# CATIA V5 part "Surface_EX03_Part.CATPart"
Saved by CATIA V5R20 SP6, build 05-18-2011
Part number: Surface_EX03_Part
Bounding box of the stored display mesh (mm): x -17.5 to 17.5, y -55.483 to 14.483, z -21 to 38.531
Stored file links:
  C:\Work\#01 CATIA Lecture Materials\#299 TOYOTA CATIA V5\TOYOTA_CATIA\LCS\Surface\Surface EX03\Surface_EX03_Part.CATPart
  C:\Work\#01 CATIA Lecture Materials\#299 TOYOTA CATIA V5\TOYOTA_CATIA\LCS\Surface\Surface EX03\Surface_EX03.CATProduct
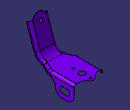
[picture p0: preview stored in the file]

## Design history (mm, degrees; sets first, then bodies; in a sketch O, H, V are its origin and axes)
Set1
  Point1: linked copy from another document
  Line1 to Line3: linked copy from another document
  Point2: linked copy from another document
  Line4 "Line.5": linked copy from another document
  Line5 "Line.6": linked copy from another document
  Line6: linked copy from another document
Set2 "Base"
  Sketch1 on Line3, origin (0, 0, 0), H (0, 1, 0), V (0, 0, 1)
    line L1 (-100, 0) -> (100, 0)
    point P1 (-100, 0)
    point P2 (100, 0)
    distance V P1 = 100
    distance P1 P2 = 200
    coincidence: P1 H
    horizontal: L1 H
  Sketch2 on Line6, origin (0, -50, 30), H (0, 0.9455, 0.3256), V (0, -0.3256, 0.9455)
    line L1 (0, 100) -> (0, -100)
    point P1 (0, 100)
    point P2 (0, -100)
    distance H P1 = 100
    distance P1 P2 = 200
    coincidence: P1 V
    vertical: L1 V
  Extrude1: Lim1 200, Lim2 200, Element1 Sketch2
  Extrude2: Lim1 200, Lim2 200, Element1 Sketch1
Set3 "Base Cut"
  Sketch3 on Line4, origin (0, -50, 30), H (-1, 0, 0), V (0, -0.3256, 0.9455)
    point P1 (-50, 4)
    line L1 (-50, 4) -> (-9.7273, 4)
    arc A1 centre (-0.2129, 0.5403) radius 8.5 from (-7.2453, 5.3149) to (6.8194, 5.3149) cw
    point P3 (0, 9.0377)
    point P4 (7.5511, 4)
    line L2 (9.3014, 4) -> (50, 4)
    point P5 (50, 4)
    arc A2 centre (-9.7273, 7) radius 3 from (-9.7273, 4) to (-7.2453, 5.3149) ccw
    arc A3 centre (9.3014, 7) radius 3 from (6.8194, 5.3149) to (9.3014, 4) ccw
    distance P1 P5 = 100
    radius A1 = 8.5
    distance H L2 = 4
    radius A2 = 3
    radius A3 = 3 {= Sketch3.radius(A2)}
    horizontal: L1 H, L2 H
    coincidence: A1 P3, P3 V, P4 L1, A1 P4, L2 P4
    symmetry: P1 P5 V
    tangency: A2 L1, A2 A1, A3 A1, A3 L2
  Sketch4 on Line3, origin (0, 0, 0), H (0, 1, 0), V (-1, 0, 0)
    point P1 (8, 50)
    line L1 (8, 50) -> (8, 11.8216)
    point P2 (8, -50)
    point P3 (13.6986, 0)
    arc A1 centre (10.5, 0) radius 4 from (12.6429, -3.3776) to (12.6429, 3.3776) ccw
    point P4 (10.5, 0)
    arc A2 centre (18, 11.8216) radius 10 from (12.6429, 3.3776) to (8, 11.8216) cw
    arc A3 centre (18, -11.8216) radius 10 from (12.6429, -3.3776) to (8, -11.8216) ccw
    point P9 (8, -11.8216)
    line L2 (8, -11.8216) -> (8, -50)
    distance P1 P2 = 100
    distance V L1 = 8
    radius A1 = 4
    distance P4 V = 10.5
    radius A2 = 10
    radius A3 = 10
    vertical: L1 V, L2 V
    symmetry: P1 P2 H
    coincidence: P4 H, L1 P9, L1 L2
    tangency: A2 A1, A2 L1, A3 A1, A3 L1
  Extrude3: Lim1 200, Lim2 200, Element1 Sketch3
  Extrude4: Lim1 200, Lim2 200, Element1 Sketch4
Set4 "Flange"
  Sketch5 on Line3, origin (0, 0, 0), H (0, 1, 0), V (-1, 0, 0)
    point P1 (-100, 11.5)
    line L1 (-100, 11.5) -> (-36.8885, 11.5)
    point P2 (-35, 11.5)
    line L2 (-33.3108, 12.3446) -> (-25.1115, 16.4443)
    point P3 (-23, 17.5)
    line L3 (-20.6393, 17.5) -> (100, 17.5)
    point P4 (100, 17.5)
    arc A1 centre (-20.6393, 7.5) radius 10 from (-25.1115, 16.4443) to (-20.6393, 17.5) cw
    arc A2 centre (-36.8885, 19.5) radius 8 from (-36.8885, 11.5) to (-33.3108, 12.3446) ccw
    distance V P1 = 100
    distance V P4 = 100
    distance V P2 = 35
    distance P3 V = 23
    distance L3 H = 17.5
    distance H L1 = 11.5
    radius A1 = 10
    radius A2 = 8
    horizontal: L1 H, L3 H
    coincidence: L2 P3, L3 P3, L1 P2, L2 P2
    tangency: A1 L2, A1 L3, A2 L1, A2 L2
  Sketch6 on Line3, origin (0, 0, 0), H (0, 1, 0), V (-1, 0, 0)
    point P1 (-100, -11.5)
    line L1 (-100, -11.5) -> (-36.8885, -11.5)
    point P2 (-35, -11.5)
    line L2 (-33.3108, -12.3446) -> (-25.1115, -16.4443)
    point P3 (-23, -17.5)
    line L3 (-20.6393, -17.5) -> (100, -17.5)
    point P4 (100, -17.5)
    arc A1 centre (-20.6393, -7.5) radius 10 from (-25.1115, -16.4443) to (-20.6393, -17.5) ccw
    arc A2 centre (-36.8885, -19.5) radius 8 from (-36.8885, -11.5) to (-33.3108, -12.3446) cw
    distance V P3 = 23
    distance V P2 = 35
    distance V P1 = 100
    distance V P4 = 100
    distance L3 H = 17.5
    distance H L1 = 11.5
    radius A1 = 10
    radius A2 = 8
    horizontal: L1 H, L3 H
    coincidence: L2 P3, L1 P2
    tangency: A1 L2, A1 L3, A2 L1, A2 L2
  Extrude5: Lim1 200, Lim2 200, Element1 Sketch5
  Extrude6: Lim1 200, Lim2 200, Element1 Sketch6
Set5 "Flange Cut"
  Sketch7 on Line6, origin (0, -50, 30), H (0, 0.9455, 0.3256), V (0, -0.3256, 0.9455)
    point P1 (20, 4)
    line L1 (20, 4) -> (-3, 4)
    line L2 (-5, 2) -> (-5, -100)
    point P2 (-5, -100)
    arc A1 centre (-3, 2) radius 2 from (-3, 4) to (-5, 2) ccw
    radius A1 = 2
    distance H L1 = 4
    distance V L2 = 5
    distance V P1 = 20
    distance H P2 = 100
    horizontal: L1 H
    vertical: L2 V
    tangency: A1 L1, A1 L2
  Sketch8 on Line3, origin (0, 0, 0), H (0, 1, 0), V (0, 0, 1)
    point P1 (-100, -5)
    line L1 (-100, -5) -> (-21.8, -5)
    line L2 (-14.8, -12) -> (-14.8, -12)
    line L3 (-5.8, -21) -> (-1, -21)
    line L4 (8, -12) -> (8, 50)
    point P2 (8, 50)
    construction line L5 (-3.4, 21.5162) -> (-3.4, -12.9024)
    arc A1 centre (-5.8, -12) radius 9 from (-14.8, -12) to (-5.8, -21) ccw
    arc A2 centre (-1, -12) radius 9 from (-1, -21) to (8, -12) ccw
    arc A3 centre (-21.8, -12) radius 7 from (-21.8, -5) to (-14.8, -12) cw
    distance L5 V = 3.4
    distance L2 L4 = 22.8
    distance H L3 = 21
    distance L1 H = 5
    distance P1 V = 100
    distance P2 H = 50
    radius A1 = 9
    radius A2 = 9 {= Sketch8.radius(A1)}
    radius A3 = 7
    horizontal: L1 H, L3 H
    vertical: L2 V, L4 V, L5 V
    symmetry: L4 L2 L5
    tangency: A1 L2, A1 L3, A2 L3, A2 L4, A3 L1, A3 L2
  Extrude7: Lim1 200, Lim2 200, Element1 Sketch7
  Extrude8: Lim1 200, Lim2 200, Element1 Sketch8
  Sketch9 on Line3, origin (0, 0, 0), H (0, 1, 0), V (0, 0, 1)
    point P1 (-100, -5)
    line L1 (-100, -5) -> (6, -5)
    line L2 (8, -3) -> (8, 50)
    point P2 (8, 50)
    arc A1 centre (6, -3) radius 2 from (6, -5) to (8, -3) ccw
    distance L1 H = 5
    distance H P2 = 50
    distance V L2 = 8
    distance V P1 = 100
    radius A1 = 2
    horizontal: L1 H
    vertical: L2 V
    tangency: A1 L1, A1 L2
  Extrude9: Lim1 200, Lim2 200, Element1 Sketch9
Set6 "Bead"
  Sketch10 on Line3, origin (0, 0, 0), H (0, 1, 0), V (0, 0, 1)
    line L1 (-12, 30) -> (-12, -0.5)
    point P2 (-12, -0.5)
    arc A1 centre (-10.5, -0.5) radius 1.5 from (-12, -0.5) to (-10.5, -2) ccw
    point P3 (-10.5, -0.5)
    line L2 (-10.5, -2) -> (-10.5, 30)
    construction line L3 (-12, 30) -> (-10.5, 30)
    radius A1 = 1.5
    distance L2 V = 10.5
    distance H P2 = 0.5
    distance H L3 = 30
    vertical: L1 V, L2 V
    tangency: A1 L1
    coincidence: P3 L2
    horizontal: L3 H
  Revol1: Element1 Sketch10, Angle1 360, Line Sketch10.L2
  Sketch11 on Line3, origin (0, 0, 0), H (0, 1, 0), V (0, 0, 1)
    line L1 (9, 30) -> (9, -0.5)
    point P2 (9, -0.5)
    arc A1 centre (10.5, -0.5) radius 1.5 from (9, -0.5) to (10.5, -2) ccw
    point P3 (10.5, -0.5)
    construction line L2 (9, 30) -> (10.5, 30)
    axis line L3 (10.5, 30) -> (10.5, -2)
    radius A1 = 1.5
    distance H P2 = 0.5
    distance H L2 = 30
    distance L3 V = 10.5
    vertical: L1 V, L3 V
    tangency: A1 L1
    horizontal: L2 H
    coincidence: P3 L3
  Revol2: Element1 Sketch11, Angle1 360
Set7 "Hole"
  Sketch12 on Line3, origin (0, 0, 0), H (0, 1, 0), V (0, 0, 1)
    construction line L1 (-3.4, 25) -> (-3.4, -25)
    point P1 (-3.4, 25)
    point P2 (-3.4, -25)
    construction line L2 (-5.9, -12) -> (-0.9, -12)
    point P3 (-5.9, -12)
    point P4 (-0.9, -12)
    line L3 (-5.9, -8.5) -> (-0.9, -8.5)
    line L4 (-0.9, -15.5) -> (-5.9, -15.5)
    arc A1 centre (-0.9, -12) radius 3.5 from (-0.9, -8.5) to (-0.9, -15.5) cw
    arc A2 centre (-5.9, -12) radius 3.5 from (-5.9, -15.5) to (-5.9, -8.5) cw
    distance L1 V = 3.4
    distance L3 L4 = 7
    distance A2 A1 = 12
    distance L2 H = 12
    length L1 = 50
    vertical: L1 V
    horizontal: L2 H
    tangency: A1 L3, A2 L3, A1 L4, A2 L4
    symmetry: L3 L4 L2, P3 P4 L1, P1 P2 H
  Sketch13 on Line4, origin (0, -50, 30), H (-1, 0, 0), V (0, -0.3256, 0.9455)
    circle A1 centre (0, 0) radius 2.25
    radius A1 = 2.25
  Sketch14 on Line3, origin (0, 0, 0), H (0, 1, 0), V (-1, 0, 0)
    circle A1 centre (0, 0) radius 3.4
    radius A1 = 3.4
  Extrude10: Lim1 200, Lim2 200, Element1 Sketch12
  Extrude11: Lim1 200, Lim2 200, Element1 Sketch13
  Extrude12: Lim1 200, Lim2 200, Element1 Sketch14
Set8 "Trim"
  Split1: ToCut Extrude5, Cutting Fillet1
  Split2: ToCut Extrude6, Cutting Fillet1
  Split3: ToCut Split2, Cutting Fillet2
  Split4: ToCut Split1, Cutting (Fillet2; Extrude9)
  Split5: ToCut Fillet1, Cutting Extrude3
  Split6: ToCut Split5, Cutting Extrude4
  Trim1: Trimmed (Split6; Revol1; Revol2)
  Split7: ToCut Trim1, Cutting Extrude11
  Split8: ToCut Split7, Cutting Extrude12
  Split9: ToCut Split3, Cutting Extrude10
Set9 "Fillet"
  Fillet1: type BiTangent, Element1 Extrude1, Element2 Extrude2, Radius 10
  Fillet2: type BiTangent, Element1 Extrude7, Element2 Extrude8, Radius 15
  Fillet3: type BiTangent, Element1 Split8, Element2 Split9, Radius 3
  Fillet4: type BiTangent, Element1 Fillet3, Element2 Split4, Radius 3
Body1 (main body)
